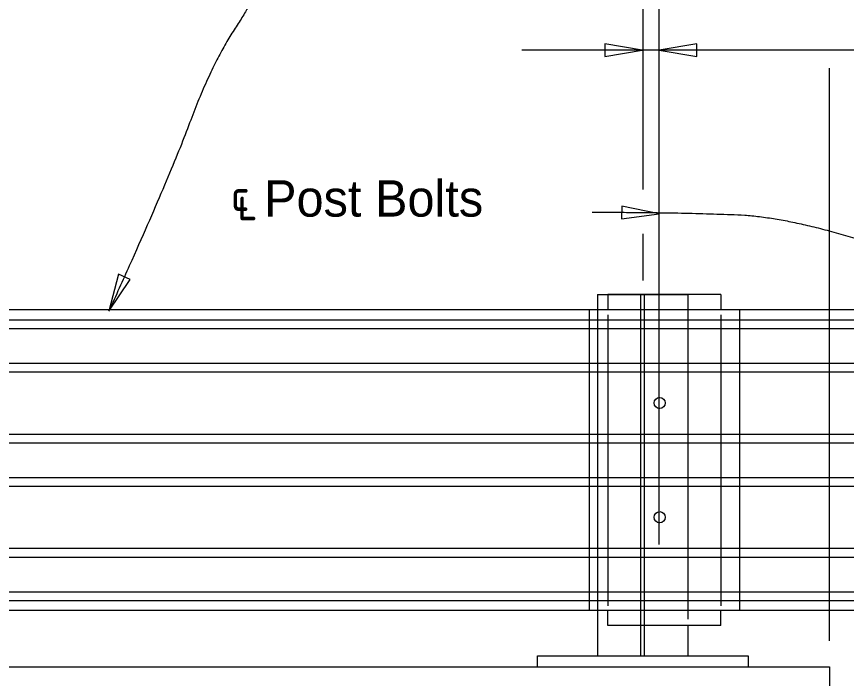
# Model space of a CAD drawing. Extents: x 21526.6 to 21595.9, y 56114.9 to 56157.2.
# Drawn here: x 21531.109 to 21535.704, y 56135.147 to 56138.813 of the extents above; entities that cross this region are included whole.
import ezdxf

# ---------------------------------------------------------------- set-up
doc = ezdxf.new("R2010")
doc.units = 0
for name, color, linetype in [('AdhocPoint_dp', 7, 'Continuous'), ('Border', 7, 'Continuous'), ('Patterning', 7, 'Continuous'), ('PlotBorder_dp', 7, 'Continuous'), ('SheetBorder_dp', 7, 'Continuous'), ('TextMisc', 7, 'Continuous')]:
    doc.layers.add(name, color=color, linetype=linetype)

msp = doc.modelspace()

# ---------------------------------------------------------------- linework, layer by layer
at = {"layer": 'AdhocPoint_dp'}
for p, q in [((21527.2426, 56135.21), (21535.6096, 56135.21)), ((21535.6096, 56135.2099), (21535.6096, 56133.7934))]:
    msp.add_line(p, q, dxfattribs=at)
at = {"layer": 'Patterning'}
for p, q in [((21534.6672, 56135.8883), (21534.6672, 56140.7989)), ((21534.5759, 56139.7166), (21534.5759, 56137.854)), ((21534.5759, 56137.6085), (21534.5759, 56137.3509)), ((21535.008, 56137.2724), (21534.383, 56137.2724)), ((21534.383, 56137.2724), (21534.383, 56137.1891)), ((21535.008, 56137.2724), (21535.008, 56137.1891)), ((21534.2788, 56137.1891), (21534.2788, 56135.5224)), ((21535.1121, 56137.1891), (21535.1121, 56135.5224)), ((21534.383, 56137.1605), (21534.383, 56135.5487)), ((21535.008, 56137.1605), (21535.008, 56135.5487)), ((21534.1592, 56137.1336), (21541.6829, 56137.1336)), ((21534.1592, 56137.0854), (21541.6829, 56137.0854)), ((21534.1592, 56136.8926), (21541.6829, 56136.8926)), ((21534.1592, 56136.8444), (21541.6829, 56136.8444)), ((21534.1592, 56136.5004), (21541.6829, 56136.5004)), ((21534.1592, 56136.4522), (21541.6829, 56136.4522)), ((21534.1592, 56136.2594), (21541.6829, 56136.2594)), ((21534.1592, 56136.2112), (21541.6829, 56136.2112)), ((21534.1592, 56135.8673), (21541.6829, 56135.8673)), ((21534.1592, 56135.8191), (21541.6829, 56135.8191)), ((21534.1592, 56135.6262), (21541.6829, 56135.6262)), ((21534.1592, 56135.578), (21541.6829, 56135.578)), ((21534.383, 56135.4391), (21534.383, 56135.5224)), ((21535.008, 56135.4391), (21535.008, 56135.5224)), ((21535.008, 56135.4391), (21534.383, 56135.4391))]:
    msp.add_line(p, q, dxfattribs=at)
at = {"layer": 'PlotBorder_dp'}
for p, q in [((21536.8702, 56138.6267), (21533.9069, 56138.6267)), ((21535.6097, 56135.3555), (21535.6097, 56138.5276))]:
    msp.add_line(p, q, dxfattribs=at)
for points in [[(21534.5735, 56138.6267), (21534.3652, 56138.662), (21534.3652, 56138.5914)], [(21534.6672, 56138.6267), (21534.8755, 56138.5914), (21534.8755, 56138.662)], [(21534.6672, 56137.7201), (21534.4604, 56137.7631), (21534.4578, 56137.6925)], [(21531.6194, 56137.1812), (21531.7378, 56137.3561), (21531.6736, 56137.3854)]]:
    msp.add_lwpolyline(points, close=True, dxfattribs=at)
for points in [[(21531.9869, 56139.2172), (21532.206, 56139.2243), (21532.4109, 56139.2031), (21532.4674, 56138.9698), (21532.1918, 56138.5598), (21531.9445, 56137.8952), (21531.6194, 56137.1812)], [(21534.2964, 56137.7285), (21534.7211, 56137.7301), (21535.4789, 56137.6995), (21536.1385, 56137.4512)]]:
    msp.add_open_spline(points, degree=2, dxfattribs=at)
at = {"layer": 'SheetBorder_dp'}
for p, q in [((21534.5655, 56135.2724), (21534.5655, 56137.2724)), ((21534.5863, 56135.2724), (21534.5863, 56137.2724)), ((21534.8259, 56137.2724), (21534.8259, 56135.4745)), ((21541.6829, 56137.1892), (21534.1592, 56137.1892)), ((21534.3259, 56137.1891), (21534.3259, 56135.5224)), ((21541.6829, 56135.5225), (21534.1592, 56135.5225))]:
    msp.add_line(p, q, dxfattribs=at)
at = {"layer": 'TextMisc'}
for p, q in [((21534.3259, 56137.2724), (21534.8259, 56137.2724)), ((21534.3259, 56137.2724), (21534.3259, 56137.1891)), ((21534.2788, 56137.1892), (21527.2426, 56137.1892)), ((21527.2426, 56137.1336), (21534.2788, 56137.1336)), ((21527.2426, 56137.0854), (21534.2788, 56137.0854)), ((21527.2426, 56136.8926), (21534.2788, 56136.8926)), ((21527.2426, 56136.8444), (21534.2788, 56136.8444)), ((21527.2426, 56136.5004), (21534.2788, 56136.5004)), ((21527.2426, 56136.4522), (21534.2788, 56136.4522)), ((21527.2426, 56136.2594), (21534.2788, 56136.2594)), ((21527.2426, 56136.2112), (21534.2788, 56136.2112)), ((21527.2426, 56135.8673), (21534.2788, 56135.8673)), ((21527.2426, 56135.8191), (21534.2788, 56135.8191)), ((21527.2426, 56135.6262), (21534.2788, 56135.6262)), ((21527.2426, 56135.578), (21534.2788, 56135.578)), ((21534.2788, 56135.5225), (21527.2426, 56135.5225)), ((21534.3259, 56135.5224), (21534.3259, 56135.2724)), ((21534.8259, 56135.4391), (21534.8259, 56135.2724)), ((21533.9926, 56135.2724), (21535.1592, 56135.2724)), ((21533.9926, 56135.2099), (21533.9926, 56135.2724)), ((21534.3259, 56135.2724), (21534.8259, 56135.2724)), ((21535.1592, 56135.2724), (21535.1592, 56135.2099)), ((21533.9926, 56135.2099), (21535.1592, 56135.2099))]:
    msp.add_line(p, q, dxfattribs=at)
for centre in [(21534.6696, 56136.6723), (21534.6696, 56136.0392)]:
    msp.add_circle(centre, 0.0312, dxfattribs=at)

# ---------------------------------------------------------------- texts
at = {"layer": 'Border'}
msp.add_text('℄ Post Bolts', height=0.2016, dxfattribs=at).set_placement((21532.2946, 56137.7047))

doc.saveas('drawing.dxf')
